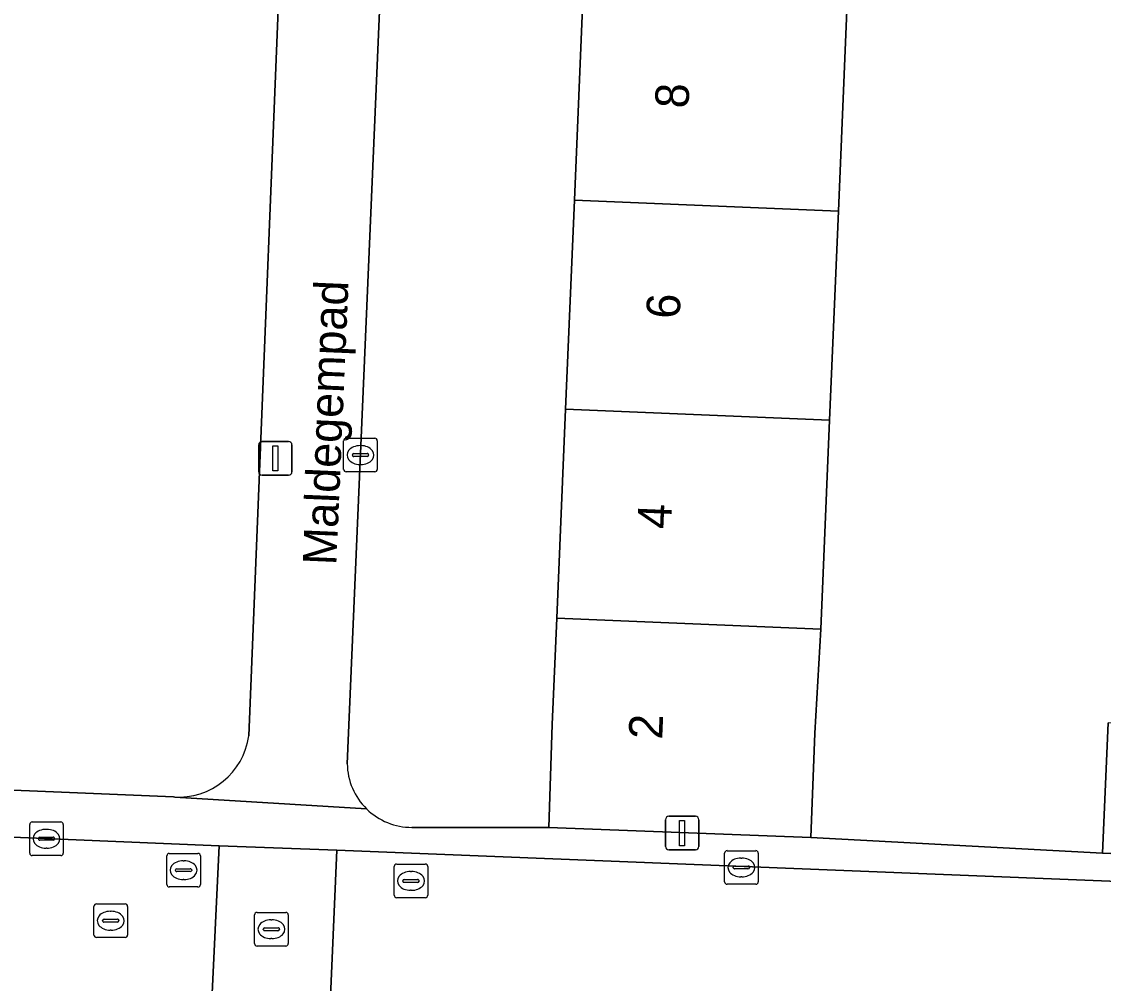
# Model space of a CAD drawing. Extents: x 160732 to 162107, y 387428 to 388479.
# Drawn here: x 161157.41 to 161189.59, y 387713.9 to 387742.52 of the extents above; entities that cross this region are included whole.
import ezdxf

# ---------------------------------------------------------------- set-up
doc = ezdxf.new("R2010")
doc.units = 0
for name, color, linetype in [('IMGEO_Erf', 7, 'Continuous'), ('IMGEO_Kolk', 7, 'Continuous'), ('IMGEO_Lichtmast', 7, 'Continuous'), ('IMGEO_Muur', 7, 'Continuous'), ('IMGEO_Openbare_ruimte_label', 7, 'Continuous'), ('IMGEO_Pand', 7, 'Continuous'), ('IMGEO_Pand_nummerreeks', 7, 'Continuous'), ('IMGEO_Rijbaan_lokaal_open', 7, 'Continuous'), ('IMGEO_Rioolput', 7, 'Continuous'), ('IMGEO_Voetpad_open', 7, 'Continuous')]:
    doc.layers.add(name, color=color, linetype=linetype)

msp = doc.modelspace()

# ---------------------------------------------------------------- linework, layer by layer
at = {"layer": 'IMGEO_Erf'}
for points in [[(161164.165, 387721.269), (161165.331, 387750), (161165.998, 387766.435)], [(161168.72, 387758.32), (161168.363, 387750), (161167.094, 387720.436)], [(161169.021, 387718.544), (161173.097, 387718.536), (161173.194, 387721.602), (161173.333, 387724.771), (161173.592, 387730.988), (161173.851, 387737.205), (161174.109, 387743.422), (161174.368, 387749.638), (161174.383, 387750), (161174.632, 387755.975), (161182.487, 387755.648), (161182.252, 387750), (161182.223, 387749.312), (161181.964, 387743.095), (161181.706, 387736.878), (161181.447, 387730.661), (161181.188, 387724.444), (161181.005, 387721.343), (161180.883, 387718.24), (161189.568, 387717.777), (161189.732, 387721.65)], [(161154.52, 387733.131), (161154.501, 387732.692), (161153.657, 387732.729), (161153.381, 387726.346), (161153.099, 387719.815), (161161.926, 387719.452)]]:
    msp.add_lwpolyline(points, dxfattribs=at)
for centre, radius, start, end in [((161162.081, 387721.548), 2.102, 265.7584, 352.3618), ((161169.013, 387720.465), 1.919, 180.8708, 225.547), ((161169.016, 387720.466), 1.922, 225.5075, 270.1464)]:
    msp.add_arc(centre, radius, start, end, dxfattribs=at)
at = {"layer": 'IMGEO_Kolk'}
for p, q in [((161166.988, 387729.197), (161166.988, 387730.049)), ((161167.063, 387730.123), (161167.915, 387730.123)), ((161167.989, 387730.049), (161167.989, 387729.197)), ((161167.247, 387729.617), (161167.247, 387729.629)), ((161167.29, 387729.666), (161167.688, 387729.666)), ((161167.476, 387729.903), (161167.501, 387729.903)), ((161167.731, 387729.629), (161167.731, 387729.617)), ((161167.685, 387729.58), (161167.287, 387729.58)), ((161167.499, 387729.343), (161167.474, 387729.343)), ((161167.915, 387729.123), (161167.063, 387729.123)), ((161157.721, 387718.706), (161158.573, 387718.706)), ((161157.646, 387717.78), (161157.646, 387718.632)), ((161158.134, 387718.486), (161158.159, 387718.486)), ((161158.647, 387718.632), (161158.647, 387717.78)), ((161157.905, 387718.2), (161157.905, 387718.212)), ((161158.343, 387718.163), (161157.945, 387718.163)), ((161157.948, 387718.249), (161158.346, 387718.249)), ((161158.389, 387718.212), (161158.389, 387718.2)), ((161158.573, 387717.706), (161157.721, 387717.706)), ((161158.157, 387717.926), (161158.132, 387717.926)), ((161178.321, 387716.925), (161178.321, 387717.777)), ((161178.396, 387717.851), (161179.248, 387717.851)), ((161179.322, 387717.777), (161179.322, 387716.925)), ((161178.623, 387717.394), (161179.021, 387717.394)), ((161178.809, 387717.631), (161178.834, 387717.631)), ((161178.58, 387717.345), (161178.58, 387717.357)), ((161179.018, 387717.308), (161178.62, 387717.308)), ((161178.832, 387717.071), (161178.807, 387717.071)), ((161179.064, 387717.357), (161179.064, 387717.345)), ((161179.248, 387716.851), (161178.396, 387716.851))]:
    msp.add_line(p, q, dxfattribs=at)
for points in [[(161166.988, 387729.197), (161166.988, 387730.049)], [(161167.063, 387730.123), (161167.915, 387730.123)], [(161167.989, 387730.049), (161167.989, 387729.197)], [(161167.915, 387729.123), (161167.063, 387729.123)], [(161157.721, 387718.706), (161158.573, 387718.706)], [(161157.646, 387717.78), (161157.646, 387718.632)], [(161158.647, 387718.632), (161158.647, 387717.78)], [(161158.573, 387717.706), (161157.721, 387717.706)], [(161178.321, 387716.925), (161178.321, 387717.777)], [(161178.396, 387717.851), (161179.248, 387717.851)], [(161179.322, 387717.777), (161179.322, 387716.925)], [(161179.248, 387716.851), (161178.396, 387716.851)]]:
    msp.add_lwpolyline(points, dxfattribs=at)
for centre, radius, start, end in [((161167.065, 387730.047), 0.0765, 91.552, 178.448), ((161167.065, 387730.047), 0.0765, 91.552, 178.448), ((161167.913, 387730.047), 0.0765, 1.552, 88.448), ((161167.913, 387730.047), 0.0765, 1.552, 88.448), ((161167.287, 387729.626), 0.0403, 85.8775, 175.7526), ((161167.284, 387729.616), 0.0366, 178.938, 274.7102), ((161167.688, 387729.623), 0.043, 264.8664, 352.4533), ((161167.692, 387729.628), 0.0386, 1.7309, 96.639), ((161167.065, 387729.199), 0.0765, 181.552, 268.448), ((161167.065, 387729.199), 0.0765, 181.552, 268.448), ((161167.913, 387729.199), 0.0765, 271.552, 358.448), ((161167.913, 387729.199), 0.0765, 271.552, 358.448), ((161157.723, 387718.63), 0.0765, 91.552, 178.448), ((161157.723, 387718.63), 0.0765, 91.552, 178.448), ((161158.571, 387718.63), 0.0765, 1.552, 88.448), ((161158.571, 387718.63), 0.0765, 1.552, 88.448), ((161157.945, 387718.209), 0.0403, 85.8775, 175.7526), ((161157.942, 387718.199), 0.0366, 178.938, 274.7102), ((161158.346, 387718.206), 0.043, 264.8664, 352.4533), ((161158.35, 387718.211), 0.0386, 1.7309, 96.639), ((161157.723, 387717.782), 0.0765, 181.552, 268.448), ((161157.723, 387717.782), 0.0765, 181.552, 268.448), ((161158.571, 387717.782), 0.0765, 271.552, 358.448), ((161158.571, 387717.782), 0.0765, 271.552, 358.448), ((161178.398, 387717.775), 0.0765, 91.552, 178.448), ((161178.398, 387717.775), 0.0765, 91.552, 178.448), ((161179.246, 387717.775), 0.0765, 1.552, 88.448), ((161179.246, 387717.775), 0.0765, 1.552, 88.448), ((161178.62, 387717.354), 0.0403, 85.8775, 175.7526), ((161179.025, 387717.356), 0.0386, 1.7309, 96.639), ((161178.617, 387717.344), 0.0366, 178.938, 274.7102), ((161179.021, 387717.351), 0.043, 264.8664, 352.4533), ((161178.398, 387716.927), 0.0765, 181.552, 268.448), ((161178.398, 387716.927), 0.0765, 181.552, 268.448), ((161179.246, 387716.927), 0.0765, 271.552, 358.448), ((161179.246, 387716.927), 0.0765, 271.552, 358.448)]:
    msp.add_arc(centre, radius, start, end, dxfattribs=at)
for centre, major_axis, ratio, start_param, end_param in [((161167.475, 387729.623), (-0.387, 0.002), 0.722429, 4.712389, 7.853982), ((161167.5, 387729.623), (-0.39, 0.002), 0.717154, 1.570796, 4.712389), ((161158.133, 387718.206), (-0.387, 0.002), 0.722429, 4.712389, 7.853982), ((161158.158, 387718.206), (-0.39, 0.002), 0.717154, 1.570796, 4.712389), ((161178.808, 387717.351), (-0.387, 0.002), 0.722429, 4.712389, 7.853982), ((161178.833, 387717.351), (-0.39, 0.002), 0.717154, 1.570796, 4.712389)]:
    msp.add_ellipse(centre, major_axis=major_axis, ratio=ratio, start_param=start_param, end_param=end_param, dxfattribs=at)
at = {"layer": 'IMGEO_Lichtmast'}
for p, q in [((161164.56, 387730.026), (161165.35, 387730.026)), ((161165.35, 387730.026), (161164.56, 387730.026)), ((161164.46, 387729.126), (161164.46, 387729.926)), ((161164.46, 387729.926), (161164.46, 387729.126)), ((161165.45, 387729.926), (161165.45, 387729.126)), ((161165.45, 387729.126), (161165.45, 387729.926)), ((161165.35, 387729.026), (161164.56, 387729.026)), ((161164.56, 387729.026), (161165.35, 387729.026)), ((161176.562, 387717.973), (161176.562, 387718.773)), ((161176.562, 387718.773), (161176.562, 387717.973)), ((161176.662, 387718.873), (161177.452, 387718.873)), ((161177.452, 387718.873), (161176.662, 387718.873)), ((161177.552, 387718.773), (161177.552, 387717.973)), ((161177.552, 387717.973), (161177.552, 387718.773)), ((161177.452, 387717.873), (161176.662, 387717.873)), ((161176.662, 387717.873), (161177.452, 387717.873))]:
    msp.add_line(p, q, dxfattribs=at)
for points in [[(161164.88, 387729.901), (161165.03, 387729.901), (161165.03, 387729.151), (161164.88, 387729.151), (161164.88, 387729.901)], [(161176.982, 387718.748), (161177.132, 387718.748), (161177.132, 387717.998), (161176.982, 387717.998), (161176.982, 387718.748)]]:
    msp.add_lwpolyline(points, dxfattribs=at)
for centre, start, end in [((161164.56, 387729.926), 90, 180), ((161164.56, 387729.926), 90, 180), ((161165.35, 387729.926), 0, 90), ((161165.35, 387729.926), 360, 90), ((161164.56, 387729.126), 180, 270), ((161164.56, 387729.126), 180, 270), ((161165.35, 387729.126), 270, 0), ((161165.35, 387729.126), 270, 0), ((161176.662, 387718.773), 90, 180), ((161176.662, 387718.773), 90, 180), ((161177.452, 387718.773), 0, 90), ((161177.452, 387718.773), 360, 90), ((161176.662, 387717.973), 180, 270), ((161176.662, 387717.973), 180, 270), ((161177.452, 387717.973), 270, 0), ((161177.452, 387717.973), 270, 0)]:
    msp.add_arc(centre, 0.1, start, end, dxfattribs=at)
at = {"layer": 'IMGEO_Muur'}
msp.add_lwpolyline([(161180.883, 387718.24), (161189.568, 387717.777)], dxfattribs=at)
at = {"layer": 'IMGEO_Pand'}
for points in [[(161174.109, 387743.422), (161173.851, 387737.205), (161181.706, 387736.878), (161181.964, 387743.095)], [(161173.851, 387737.205), (161173.592, 387730.988), (161181.447, 387730.661), (161181.706, 387736.878)], [(161181.188, 387724.444), (161181.447, 387730.661), (161173.592, 387730.988), (161173.333, 387724.771)], [(161180.883, 387718.24), (161181.005, 387721.343), (161181.188, 387724.444), (161173.333, 387724.771), (161173.194, 387721.602), (161173.097, 387718.536)], [(161192.006, 387717.674), (161192.17, 387721.547), (161189.732, 387721.65), (161189.568, 387717.777)]]:
    msp.add_lwpolyline(points, close=True, dxfattribs=at)
at = {"layer": 'IMGEO_Rijbaan_lokaal_open'}
for points in [[(161118.607, 387714.859), (161154.97, 387713.35), (161163.047, 387712.981), (161163.287, 387717.997), (161123.552, 387719.662)], [(161231.579, 387715.221), (161192.747, 387716.82), (161166.782, 387717.863), (161166.569, 387712.818), (161190.77, 387711.86), (161192.634, 387711.802), (161235.923, 387710.068), (161258.15, 387709.198), (161259.239, 387709.146)]]:
    msp.add_lwpolyline(points, dxfattribs=at)
msp.add_lwpolyline([(161166.569, 387712.818), (161166.782, 387717.863), (161163.287, 387717.997), (161163.047, 387712.981)], close=True, dxfattribs=at)
at = {"layer": 'IMGEO_Rioolput'}
for p, q in [((161161.8, 387717.77), (161162.652, 387717.77)), ((161161.725, 387716.844), (161161.725, 387717.696)), ((161162.213, 387717.55), (161162.238, 387717.55)), ((161162.726, 387717.696), (161162.726, 387716.844)), ((161168.49, 387716.525), (161168.49, 387717.377)), ((161168.565, 387717.451), (161169.417, 387717.451)), ((161169.491, 387717.377), (161169.491, 387716.525)), ((161161.984, 387717.264), (161161.984, 387717.276)), ((161162.422, 387717.227), (161162.024, 387717.227)), ((161162.027, 387717.313), (161162.425, 387717.313)), ((161162.468, 387717.276), (161162.468, 387717.264)), ((161168.978, 387717.231), (161169.003, 387717.231)), ((161162.652, 387716.77), (161161.8, 387716.77)), ((161162.236, 387716.99), (161162.211, 387716.99)), ((161168.749, 387716.945), (161168.749, 387716.957)), ((161169.187, 387716.908), (161168.789, 387716.908)), ((161168.792, 387716.994), (161169.19, 387716.994)), ((161169.233, 387716.957), (161169.233, 387716.945)), ((161169.417, 387716.451), (161168.565, 387716.451)), ((161169.001, 387716.671), (161168.976, 387716.671)), ((161159.557, 387715.341), (161159.557, 387716.193)), ((161159.632, 387716.267), (161160.484, 387716.267)), ((161160.558, 387716.193), (161160.558, 387715.341)), ((161159.816, 387715.761), (161159.816, 387715.773)), ((161159.859, 387715.81), (161160.257, 387715.81)), ((161160.045, 387716.047), (161160.07, 387716.047)), ((161160.3, 387715.773), (161160.3, 387715.761)), ((161164.337, 387715.087), (161164.337, 387715.939)), ((161164.412, 387716.013), (161165.264, 387716.013)), ((161164.825, 387715.793), (161164.85, 387715.793)), ((161165.338, 387715.939), (161165.338, 387715.087)), ((161160.254, 387715.724), (161159.856, 387715.724)), ((161160.068, 387715.487), (161160.043, 387715.487)), ((161164.596, 387715.507), (161164.596, 387715.519)), ((161165.034, 387715.47), (161164.636, 387715.47)), ((161164.639, 387715.556), (161165.037, 387715.556)), ((161165.08, 387715.519), (161165.08, 387715.507)), ((161160.484, 387715.267), (161159.632, 387715.267)), ((161164.848, 387715.233), (161164.823, 387715.233)), ((161165.264, 387715.013), (161164.412, 387715.013))]:
    msp.add_line(p, q, dxfattribs=at)
for points in [[(161161.8, 387717.77), (161162.652, 387717.77)], [(161161.725, 387716.844), (161161.725, 387717.696)], [(161162.726, 387717.696), (161162.726, 387716.844)], [(161168.49, 387716.525), (161168.49, 387717.377)], [(161168.565, 387717.451), (161169.417, 387717.451)], [(161169.491, 387717.377), (161169.491, 387716.525)], [(161162.652, 387716.77), (161161.8, 387716.77)], [(161169.417, 387716.451), (161168.565, 387716.451)], [(161159.557, 387715.341), (161159.557, 387716.193)], [(161159.632, 387716.267), (161160.484, 387716.267)], [(161160.558, 387716.193), (161160.558, 387715.341)], [(161164.337, 387715.087), (161164.337, 387715.939)], [(161164.412, 387716.013), (161165.264, 387716.013)], [(161165.338, 387715.939), (161165.338, 387715.087)], [(161160.484, 387715.267), (161159.632, 387715.267)], [(161165.264, 387715.013), (161164.412, 387715.013)]]:
    msp.add_lwpolyline(points, dxfattribs=at)
for centre, radius, start, end in [((161161.802, 387717.694), 0.0765, 91.552, 178.448), ((161161.802, 387717.694), 0.0765, 91.552, 178.448), ((161162.65, 387717.694), 0.0765, 1.552, 88.448), ((161162.65, 387717.694), 0.0765, 1.552, 88.448), ((161168.567, 387717.375), 0.0765, 91.552, 178.448), ((161168.567, 387717.375), 0.0765, 91.552, 178.448), ((161169.415, 387717.375), 0.0765, 1.552, 88.448), ((161169.415, 387717.375), 0.0765, 1.552, 88.448), ((161162.024, 387717.273), 0.0403, 85.8775, 175.7526), ((161162.021, 387717.263), 0.0366, 178.938, 274.7102), ((161162.425, 387717.27), 0.043, 264.8664, 352.4533), ((161162.429, 387717.275), 0.0386, 1.7309, 96.639), ((161161.802, 387716.846), 0.0765, 181.552, 268.448), ((161161.802, 387716.846), 0.0765, 181.552, 268.448), ((161162.65, 387716.846), 0.0765, 271.552, 358.448), ((161162.65, 387716.846), 0.0765, 271.552, 358.448), ((161168.789, 387716.954), 0.0403, 85.8775, 175.7526), ((161168.786, 387716.944), 0.0366, 178.938, 274.7102), ((161169.19, 387716.951), 0.043, 264.8664, 352.4533), ((161169.194, 387716.956), 0.0386, 1.7309, 96.639), ((161168.567, 387716.527), 0.0765, 181.552, 268.448), ((161168.567, 387716.527), 0.0765, 181.552, 268.448), ((161169.415, 387716.527), 0.0765, 271.552, 358.448), ((161169.415, 387716.527), 0.0765, 271.552, 358.448), ((161159.634, 387716.191), 0.0765, 91.552, 178.448), ((161159.634, 387716.191), 0.0765, 91.552, 178.448), ((161160.482, 387716.191), 0.0765, 1.552, 88.448), ((161160.482, 387716.191), 0.0765, 1.552, 88.448), ((161159.856, 387715.77), 0.0403, 85.8775, 175.7526), ((161160.261, 387715.772), 0.0386, 1.7309, 96.639), ((161164.414, 387715.937), 0.0765, 91.552, 178.448), ((161164.414, 387715.937), 0.0765, 91.552, 178.448), ((161165.262, 387715.937), 0.0765, 1.552, 88.448), ((161165.262, 387715.937), 0.0765, 1.552, 88.448), ((161159.853, 387715.76), 0.0366, 178.938, 274.7102), ((161160.257, 387715.767), 0.043, 264.8664, 352.4533), ((161164.636, 387715.516), 0.0403, 85.8775, 175.7526), ((161164.633, 387715.506), 0.0366, 178.938, 274.7102), ((161165.037, 387715.513), 0.043, 264.8664, 352.4533), ((161165.041, 387715.518), 0.0386, 1.7309, 96.639), ((161159.634, 387715.343), 0.0765, 181.552, 268.448), ((161159.634, 387715.343), 0.0765, 181.552, 268.448), ((161160.482, 387715.343), 0.0765, 271.552, 358.448), ((161160.482, 387715.343), 0.0765, 271.552, 358.448), ((161164.414, 387715.089), 0.0765, 181.552, 268.448), ((161164.414, 387715.089), 0.0765, 181.552, 268.448), ((161165.262, 387715.089), 0.0765, 271.552, 358.448), ((161165.262, 387715.089), 0.0765, 271.552, 358.448)]:
    msp.add_arc(centre, radius, start, end, dxfattribs=at)
for centre, major_axis, ratio, start_param, end_param in [((161162.212, 387717.27), (-0.387, 0.002), 0.722429, 4.712389, 7.853982), ((161162.237, 387717.27), (-0.39, 0.002), 0.717154, 1.570796, 4.712389), ((161168.977, 387716.951), (-0.387, 0.002), 0.722429, 4.712389, 7.853982), ((161169.002, 387716.951), (-0.39, 0.002), 0.717154, 1.570796, 4.712389), ((161160.044, 387715.767), (-0.387, 0.002), 0.722429, 4.712389, 7.853982), ((161160.069, 387715.767), (-0.39, 0.002), 0.717154, 1.570796, 4.712389), ((161164.824, 387715.513), (-0.387, 0.002), 0.722429, 4.712389, 7.853982), ((161164.849, 387715.513), (-0.39, 0.002), 0.717154, 1.570796, 4.712389)]:
    msp.add_ellipse(centre, major_axis=major_axis, ratio=ratio, start_param=start_param, end_param=end_param, dxfattribs=at)
at = {"layer": 'IMGEO_Voetpad_open'}
for points in [[(161167.669, 387719.095), (161161.967, 387719.446), (161161.926, 387719.452), (161153.099, 387719.815), (161143.568, 387720.283), (161133.639, 387720.538), (161128.149, 387720.759), (161126.139, 387720.772), (161124.114, 387720.835), (161124.438, 387727.592), (161125.573, 387756.28), (161125.698, 387759.448), (161126.042, 387768.14)], [(161165.998, 387766.435), (161165.331, 387750), (161164.165, 387721.269)], [(161167.094, 387720.436), (161168.363, 387750)], [(161193.715, 387717.763), (161193.964, 387723.667), (161193.77, 387723.675), (161192.223, 387723.698), (161192.151, 387722.091), (161192.17, 387721.547), (161192.006, 387717.674), (161189.568, 387717.777), (161180.883, 387718.24), (161173.097, 387718.536), (161169.021, 387718.544)], [(161123.552, 387719.662), (161163.287, 387717.997), (161166.782, 387717.863), (161192.747, 387716.82)], [(161161.926, 387719.452), (161161.967, 387719.446), (161167.669, 387719.095)]]:
    msp.add_lwpolyline(points, dxfattribs=at)
for centre, radius, start, end in [((161162.081, 387721.548), 2.102, 265.7584, 352.3618), ((161169.013, 387720.465), 1.919, 180.8708, 225.547), ((161169.016, 387720.466), 1.922, 225.5075, 270.1464)]:
    msp.add_arc(centre, radius, start, end, dxfattribs=at)

# ---------------------------------------------------------------- texts
at = {"layer": 'IMGEO_Openbare_ruimte_label'}
msp.add_text('Maldegempad', height=1, rotation=87.5353, dxfattribs=at).set_placement((161166.768, 387726.332))
at = {"layer": 'IMGEO_Pand_nummerreeks'}
for s, p in [('8', (161177.246, 387739.926)), ('6', (161176.986, 387733.665)), ('4', (161176.725, 387727.408)), ('2', (161176.465, 387721.149))]:
    msp.add_text(s, height=1, rotation=87.616, dxfattribs=at).set_placement(p)

doc.saveas('drawing.dxf')
